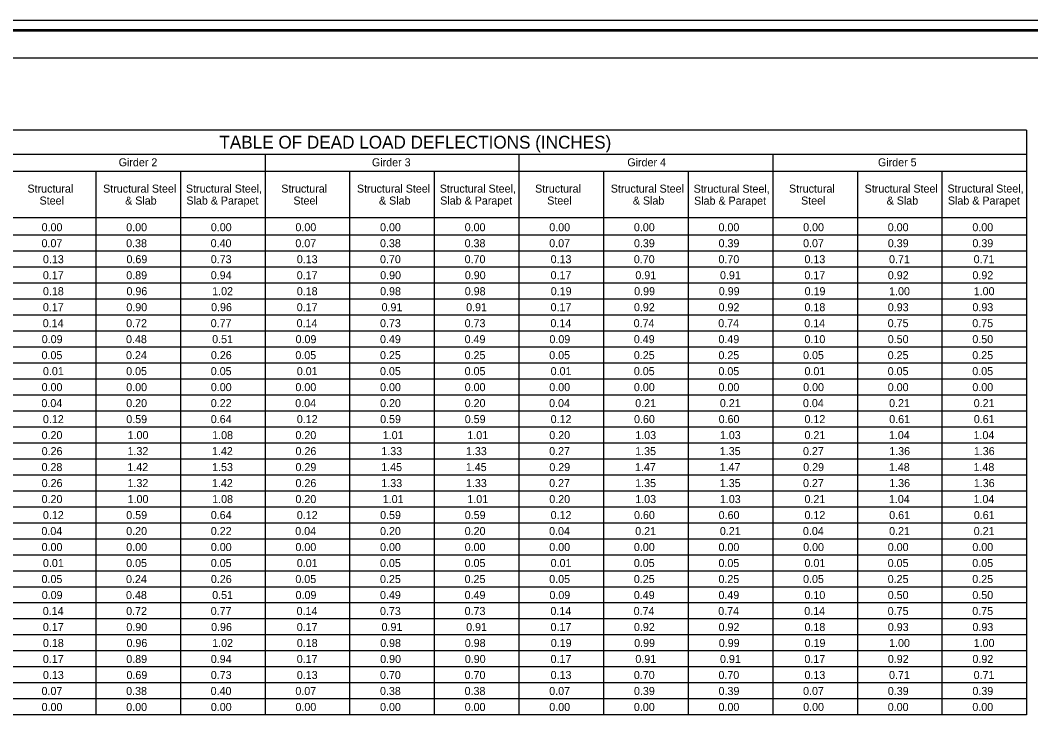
# Model space of a CAD drawing. Extents: x 208.5 to 250.5, y 328.7 to 350.7.
# Drawn here: x 216.62 to 232.41, y 339.65 to 350.71 of the extents above; entities that cross this region are included whole.
import ezdxf

# ---------------------------------------------------------------- set-up
doc = ezdxf.new("R2010")
doc.units = 0
for name, color, linetype in [('border', 7, 'Continuous'), ('Border 2660-Hwy18 - Level 62', 7, 'Continuous'), ('Border 2660-Hwy18 - Level 63', 7, 'Continuous'), ('Level 62 PDF', 7, 'Continuous'), ('Steel', 7, 'Continuous'), ('Text', 7, 'Continuous'), ('Title Text', 7, 'Continuous')]:
    doc.layers.add(name, color=color, linetype=linetype)

msp = doc.modelspace()

# ---------------------------------------------------------------- linework, layer by layer
at = {"layer": 'border'}
msp.add_line((210.28, 350.129), (242.291, 350.129), dxfattribs=at)
at = {"layer": 'Border 2660-Hwy18 - Level 62'}
msp.add_lwpolyline([(208.659, 350.715), (242.778, 350.715), (242.778, 328.905), (208.659, 328.905)], close=True, dxfattribs=at)
at = {"layer": 'Border 2660-Hwy18 - Level 63'}
msp.add_lwpolyline([(208.548, 350.572), (242.548, 350.572), (242.548, 329.202), (208.548, 329.202)], close=True, dxfattribs=at)
at = {"layer": 'Level 62 PDF'}
msp.add_lwpolyline([(208.909, 350.548), (243.028, 350.548), (243.028, 328.739), (208.909, 328.739)], close=True, dxfattribs=at)
at = {"layer": 'Steel'}
for p, q in [((232.347, 348.995), (210.932, 348.995)), ((232.347, 348.995), (232.347, 339.854)), ((232.347, 348.618), (210.932, 348.618)), ((220.449, 348.618), (220.449, 339.854)), ((224.415, 348.618), (224.415, 339.854)), ((228.381, 348.618), (228.381, 339.854)), ((232.347, 348.349), (212.517, 348.349)), ((217.805, 348.349), (217.805, 339.854)), ((219.127, 348.349), (219.127, 339.854)), ((221.771, 348.349), (221.771, 339.854)), ((223.093, 348.349), (223.093, 339.854)), ((225.737, 348.349), (225.737, 339.854)), ((227.059, 348.349), (227.059, 339.854)), ((229.703, 348.349), (229.703, 339.854)), ((231.025, 348.349), (231.025, 339.854)), ((232.347, 347.623), (210.932, 347.623)), ((232.347, 347.354), (211.725, 347.354)), ((232.347, 347.104), (211.725, 347.104)), ((232.347, 346.854), (211.725, 346.854)), ((232.347, 346.604), (211.725, 346.604)), ((232.347, 346.354), (211.725, 346.354)), ((232.347, 346.104), (211.725, 346.104)), ((232.347, 345.854), (211.725, 345.854)), ((232.347, 345.604), (211.725, 345.604)), ((232.347, 345.354), (211.725, 345.354)), ((232.347, 345.104), (211.725, 345.104)), ((232.347, 344.854), (211.725, 344.854)), ((232.347, 344.604), (211.725, 344.604)), ((232.347, 344.354), (211.725, 344.354)), ((232.347, 344.104), (211.725, 344.104)), ((232.347, 343.854), (211.725, 343.854)), ((232.347, 343.604), (211.725, 343.604)), ((232.347, 343.354), (211.725, 343.354)), ((232.347, 343.104), (211.725, 343.104)), ((232.347, 342.854), (211.725, 342.854)), ((232.347, 342.604), (211.725, 342.604)), ((232.347, 342.354), (211.725, 342.354)), ((232.347, 342.104), (211.725, 342.104)), ((232.347, 341.854), (211.725, 341.854)), ((232.347, 341.604), (211.725, 341.604)), ((232.347, 341.354), (211.725, 341.354)), ((232.347, 341.104), (211.725, 341.104)), ((232.347, 340.854), (211.725, 340.854)), ((232.347, 340.604), (211.725, 340.604)), ((232.347, 340.354), (211.725, 340.354)), ((232.347, 340.104), (211.725, 340.104)), ((232.347, 339.854), (210.932, 339.854))]:
    msp.add_line(p, q, dxfattribs=at)

# ---------------------------------------------------------------- texts
at = {"layer": 'Text'}
for s, p in [('Girder 2', (218.162, 348.431)), ('Girder 3', (222.119, 348.431)), ('Girder 4', (226.109, 348.431)), ('Girder 5', (230.025, 348.431)), ('Structural', (216.737, 348.02)), ('Structural Steel', (217.919, 348.02)), ('Structural Steel,', (219.213, 348.02)), ('Structural', (220.703, 348.02)), ('Structural Steel', (221.885, 348.02)), ('Structural Steel,', (223.179, 348.02)), ('Structural', (224.669, 348.02)), ('Structural Steel', (225.851, 348.02)), ('Structural Steel,', (227.145, 348.018)), ('Structural', (228.635, 348.02)), ('Structural Steel', (229.817, 348.02)), ('Structural Steel,', (231.111, 348.021)), ('Steel', (216.926, 347.833)), ('& Slab', (218.263, 347.833)), ('Slab & Parapet', (219.22, 347.833)), ('Steel', (220.892, 347.833)), ('& Slab', (222.229, 347.833)), ('Slab & Parapet', (223.186, 347.833)), ('Steel', (224.858, 347.833)), ('& Slab', (226.195, 347.833)), ('Slab & Parapet', (227.152, 347.831)), ('Steel', (228.824, 347.833)), ('& Slab', (230.161, 347.833)), ('Slab & Parapet', (231.118, 347.833)), ('0.00', (216.958, 347.416)), ('0.00', (218.28, 347.416)), ('0.00', (219.602, 347.416)), ('0.00', (220.924, 347.416)), ('0.00', (222.246, 347.416)), ('0.00', (223.568, 347.416)), ('0.00', (224.89, 347.416)), ('0.00', (226.212, 347.416)), ('0.00', (227.534, 347.416)), ('0.00', (228.856, 347.416)), ('0.00', (230.178, 347.416)), ('0.00', (231.5, 347.416)), ('0.07', (216.957, 347.166)), ('0.38', (218.279, 347.166)), ('0.40', (219.599, 347.166)), ('0.07', (220.923, 347.166)), ('0.38', (222.245, 347.166)), ('0.38', (223.567, 347.166)), ('0.07', (224.889, 347.166)), ('0.39', (226.213, 347.166)), ('0.39', (227.535, 347.166)), ('0.07', (228.855, 347.166)), ('0.39', (230.179, 347.166)), ('0.39', (231.501, 347.166)), ('0.13', (216.979, 346.916)), ('0.69', (218.284, 346.916)), ('0.73', (219.601, 346.916)), ('0.13', (220.945, 346.916)), ('0.70', (222.245, 346.916)), ('0.70', (223.567, 346.916)), ('0.13', (224.911, 346.916)), ('0.70', (226.211, 346.916)), ('0.70', (227.533, 346.916)), ('0.13', (228.877, 346.916)), ('0.71', (230.198, 346.916)), ('0.71', (231.52, 346.916)), ('0.17', (216.978, 346.666)), ('0.89', (218.281, 346.666)), ('0.94', (219.601, 346.666)), ('0.17', (220.944, 346.666)), ('0.90', (222.248, 346.666)), ('0.90', (223.57, 346.666)), ('0.17', (224.91, 346.666)), ('0.91', (226.235, 346.666)), ('0.91', (227.557, 346.666)), ('0.17', (228.876, 346.666)), ('0.92', (230.179, 346.666)), ('0.92', (231.501, 346.666)), ('0.18', (216.979, 346.416)), ('0.96', (218.284, 346.416)), ('1.02', (219.623, 346.416)), ('0.18', (220.945, 346.416)), ('0.98', (222.247, 346.416)), ('0.98', (223.569, 346.416)), ('0.19', (224.913, 346.416)), ('0.99', (226.216, 346.416)), ('0.99', (227.538, 346.416)), ('0.19', (228.879, 346.416)), ('1.00', (230.199, 346.416)), ('1.00', (231.521, 346.416)), ('0.17', (216.978, 346.166)), ('0.90', (218.282, 346.166)), ('0.96', (219.606, 346.166)), ('0.17', (220.944, 346.166)), ('0.91', (222.269, 346.166)), ('0.91', (223.591, 346.166)), ('0.17', (224.91, 346.166)), ('0.92', (226.213, 346.166)), ('0.92', (227.535, 346.166)), ('0.18', (228.877, 346.166)), ('0.93', (230.179, 346.166)), ('0.93', (231.501, 346.166)), ('0.14', (216.976, 345.916)), ('0.72', (218.279, 345.916)), ('0.77', (219.6, 345.916)), ('0.14', (220.942, 345.916)), ('0.73', (222.245, 345.916)), ('0.73', (223.567, 345.916)), ('0.14', (224.908, 345.916)), ('0.74', (226.208, 345.916)), ('0.74', (227.53, 345.916)), ('0.14', (228.874, 345.916)), ('0.75', (230.177, 345.916)), ('0.75', (231.499, 345.916)), ('0.09', (216.96, 345.666)), ('0.48', (218.277, 345.666)), ('0.51', (219.623, 345.666)), ('0.09', (220.926, 345.666)), ('0.49', (222.245, 345.666)), ('0.49', (223.567, 345.666)), ('0.09', (224.892, 345.666)), ('0.49', (226.211, 345.666)), ('0.49', (227.533, 345.666)), ('0.10', (228.877, 345.666)), ('0.50', (230.178, 345.666)), ('0.50', (231.5, 345.666)), ('0.05', (216.957, 345.416)), ('0.24', (218.277, 345.416)), ('0.26', (219.603, 345.416)), ('0.05', (220.923, 345.416)), ('0.25', (222.245, 345.416)), ('0.25', (223.567, 345.416)), ('0.05', (224.889, 345.416)), ('0.25', (226.211, 345.416)), ('0.25', (227.533, 345.416)), ('0.05', (228.855, 345.416)), ('0.25', (230.177, 345.416)), ('0.25', (231.499, 345.416)), ('0.01', (216.979, 345.166)), ('0.05', (218.279, 345.166)), ('0.05', (219.601, 345.166)), ('0.01', (220.945, 345.166)), ('0.05', (222.245, 345.166)), ('0.05', (223.567, 345.166)), ('0.01', (224.911, 345.166)), ('0.05', (226.211, 345.166)), ('0.05', (227.533, 345.166)), ('0.01', (228.877, 345.166)), ('0.05', (230.177, 345.166)), ('0.05', (231.499, 345.166)), ('0.00', (216.958, 344.916)), ('0.00', (218.28, 344.916)), ('0.00', (219.602, 344.916)), ('0.00', (220.924, 344.916)), ('0.00', (222.246, 344.916)), ('0.00', (223.568, 344.916)), ('0.00', (224.89, 344.916)), ('0.00', (226.212, 344.916)), ('0.00', (227.534, 344.916)), ('0.00', (228.856, 344.916)), ('0.00', (230.178, 344.916)), ('0.00', (231.5, 344.916)), ('0.04', (216.955, 344.666)), ('0.20', (218.28, 344.666)), ('0.22', (219.601, 344.666)), ('0.04', (220.921, 344.666)), ('0.20', (222.246, 344.666)), ('0.20', (223.568, 344.666)), ('0.04', (224.887, 344.666)), ('0.21', (226.233, 344.666)), ('0.21', (227.555, 344.666)), ('0.04', (228.853, 344.666)), ('0.21', (230.199, 344.666)), ('0.21', (231.521, 344.666)), ('0.12', (216.979, 344.416)), ('0.59', (218.281, 344.416)), ('0.64', (219.601, 344.416)), ('0.12', (220.945, 344.416)), ('0.59', (222.247, 344.416)), ('0.59', (223.569, 344.416)), ('0.12', (224.911, 344.416)), ('0.60', (226.214, 344.416)), ('0.60', (227.536, 344.416)), ('0.12', (228.877, 344.416)), ('0.61', (230.201, 344.416)), ('0.61', (231.523, 344.416)), ('0.20', (216.958, 344.166)), ('1.00', (218.302, 344.166)), ('1.08', (219.623, 344.166)), ('0.20', (220.924, 344.166)), ('1.01', (222.288, 344.166)), ('1.01', (223.61, 344.166)), ('0.20', (224.89, 344.166)), ('1.03', (226.233, 344.166)), ('1.03', (227.555, 344.166)), ('0.21', (228.877, 344.166)), ('1.04', (230.196, 344.166)), ('1.04', (231.518, 344.166)), ('0.26', (216.959, 343.916)), ('1.32', (218.3, 343.916)), ('1.42', (219.62, 343.916)), ('0.26', (220.925, 343.916)), ('1.33', (222.266, 343.916)), ('1.33', (223.588, 343.916)), ('0.27', (224.888, 343.916)), ('1.35', (226.232, 343.916)), ('1.35', (227.554, 343.916)), ('0.27', (228.854, 343.916)), ('1.36', (230.201, 343.916)), ('1.36', (231.523, 343.916)), ('0.28', (216.957, 343.666)), ('1.42', (218.298, 343.666)), ('1.53', (219.622, 343.666)), ('0.29', (220.925, 343.666)), ('1.45', (222.264, 343.666)), ('1.45', (223.586, 343.666)), ('0.29', (224.891, 343.666)), ('1.47', (226.229, 343.666)), ('1.47', (227.551, 343.666)), ('0.29', (228.857, 343.666)), ('1.48', (230.196, 343.666)), ('1.48', (231.518, 343.666)), ('0.26', (216.959, 343.416)), ('1.32', (218.3, 343.416)), ('1.42', (219.62, 343.416)), ('0.26', (220.925, 343.416)), ('1.33', (222.266, 343.416)), ('1.33', (223.588, 343.416)), ('0.27', (224.888, 343.416)), ('1.35', (226.232, 343.416)), ('1.35', (227.554, 343.416)), ('0.27', (228.854, 343.416)), ('1.36', (230.201, 343.416)), ('1.36', (231.523, 343.416)), ('0.20', (216.958, 343.166)), ('1.00', (218.302, 343.166)), ('1.08', (219.623, 343.166)), ('0.20', (220.924, 343.166)), ('1.01', (222.288, 343.166)), ('1.01', (223.61, 343.166)), ('0.20', (224.89, 343.166)), ('1.03', (226.233, 343.166)), ('1.03', (227.555, 343.166)), ('0.21', (228.877, 343.166)), ('1.04', (230.196, 343.166)), ('1.04', (231.518, 343.166)), ('0.12', (216.979, 342.916)), ('0.59', (218.281, 342.916)), ('0.64', (219.601, 342.916)), ('0.12', (220.945, 342.916)), ('0.59', (222.247, 342.916)), ('0.59', (223.569, 342.916)), ('0.12', (224.911, 342.916)), ('0.60', (226.214, 342.916)), ('0.60', (227.536, 342.916)), ('0.12', (228.877, 342.916)), ('0.61', (230.201, 342.916)), ('0.61', (231.523, 342.916)), ('0.04', (216.955, 342.666)), ('0.20', (218.28, 342.666)), ('0.22', (219.601, 342.666)), ('0.04', (220.921, 342.666)), ('0.20', (222.246, 342.666)), ('0.20', (223.568, 342.666)), ('0.04', (224.887, 342.666)), ('0.21', (226.233, 342.666)), ('0.21', (227.555, 342.666)), ('0.04', (228.853, 342.666)), ('0.21', (230.199, 342.666)), ('0.21', (231.521, 342.666)), ('0.00', (216.958, 342.416)), ('0.00', (218.28, 342.416)), ('0.00', (219.602, 342.416)), ('0.00', (220.924, 342.416)), ('0.00', (222.246, 342.416)), ('0.00', (223.568, 342.416)), ('0.00', (224.89, 342.416)), ('0.00', (226.212, 342.416)), ('0.00', (227.534, 342.416)), ('0.00', (228.856, 342.416)), ('0.00', (230.178, 342.416)), ('0.00', (231.5, 342.416)), ('0.01', (216.979, 342.166)), ('0.05', (218.279, 342.166)), ('0.05', (219.601, 342.166)), ('0.01', (220.945, 342.166)), ('0.05', (222.245, 342.166)), ('0.05', (223.567, 342.166)), ('0.01', (224.911, 342.166)), ('0.05', (226.211, 342.166)), ('0.05', (227.533, 342.166)), ('0.01', (228.877, 342.166)), ('0.05', (230.177, 342.166)), ('0.05', (231.499, 342.166)), ('0.05', (216.957, 341.916)), ('0.24', (218.277, 341.916)), ('0.26', (219.603, 341.916)), ('0.05', (220.923, 341.916)), ('0.25', (222.245, 341.916)), ('0.25', (223.567, 341.916)), ('0.05', (224.889, 341.916)), ('0.25', (226.211, 341.916)), ('0.25', (227.533, 341.916)), ('0.05', (228.855, 341.916)), ('0.25', (230.177, 341.916)), ('0.25', (231.499, 341.916)), ('0.09', (216.96, 341.666)), ('0.48', (218.277, 341.666)), ('0.51', (219.623, 341.666)), ('0.09', (220.926, 341.666)), ('0.49', (222.245, 341.666)), ('0.49', (223.567, 341.666)), ('0.09', (224.892, 341.666)), ('0.49', (226.211, 341.666)), ('0.49', (227.533, 341.666)), ('0.10', (228.877, 341.666)), ('0.50', (230.178, 341.666)), ('0.50', (231.5, 341.666)), ('0.14', (216.976, 341.416)), ('0.72', (218.279, 341.416)), ('0.77', (219.6, 341.416)), ('0.14', (220.942, 341.416)), ('0.73', (222.245, 341.416)), ('0.73', (223.567, 341.416)), ('0.14', (224.908, 341.416)), ('0.74', (226.208, 341.416)), ('0.74', (227.53, 341.416)), ('0.14', (228.874, 341.416)), ('0.75', (230.177, 341.416)), ('0.75', (231.499, 341.416)), ('0.17', (216.978, 341.166)), ('0.90', (218.282, 341.166)), ('0.96', (219.606, 341.166)), ('0.17', (220.944, 341.166)), ('0.91', (222.269, 341.166)), ('0.91', (223.591, 341.166)), ('0.17', (224.91, 341.166)), ('0.92', (226.213, 341.166)), ('0.92', (227.535, 341.166)), ('0.18', (228.877, 341.166)), ('0.93', (230.179, 341.166)), ('0.93', (231.501, 341.166)), ('0.18', (216.979, 340.916)), ('0.96', (218.284, 340.916)), ('1.02', (219.623, 340.916)), ('0.18', (220.945, 340.916)), ('0.98', (222.247, 340.916)), ('0.98', (223.569, 340.916)), ('0.19', (224.913, 340.916)), ('0.99', (226.216, 340.916)), ('0.99', (227.538, 340.916)), ('0.19', (228.879, 340.916)), ('1.00', (230.199, 340.916)), ('1.00', (231.521, 340.916)), ('0.17', (216.978, 340.666)), ('0.89', (218.281, 340.666)), ('0.94', (219.601, 340.666)), ('0.17', (220.944, 340.666)), ('0.90', (222.248, 340.666)), ('0.90', (223.57, 340.666)), ('0.17', (224.91, 340.666)), ('0.91', (226.235, 340.666)), ('0.91', (227.557, 340.666)), ('0.17', (228.876, 340.666)), ('0.92', (230.179, 340.666)), ('0.92', (231.501, 340.666)), ('0.13', (216.979, 340.416)), ('0.69', (218.284, 340.416)), ('0.73', (219.601, 340.416)), ('0.13', (220.945, 340.416)), ('0.70', (222.245, 340.416)), ('0.70', (223.567, 340.416)), ('0.13', (224.911, 340.416)), ('0.70', (226.211, 340.416)), ('0.70', (227.533, 340.416)), ('0.13', (228.877, 340.416)), ('0.71', (230.198, 340.416)), ('0.71', (231.52, 340.416)), ('0.07', (216.957, 340.166)), ('0.38', (218.279, 340.166)), ('0.40', (219.599, 340.166)), ('0.07', (220.923, 340.166)), ('0.38', (222.245, 340.166)), ('0.38', (223.567, 340.166)), ('0.07', (224.889, 340.166)), ('0.39', (226.213, 340.166)), ('0.39', (227.535, 340.166)), ('0.07', (228.855, 340.166)), ('0.39', (230.179, 340.166)), ('0.39', (231.501, 340.166)), ('0.00', (216.958, 339.916)), ('0.00', (218.28, 339.916)), ('0.00', (219.602, 339.916)), ('0.00', (220.924, 339.916)), ('0.00', (222.246, 339.916)), ('0.00', (223.568, 339.916)), ('0.00', (224.89, 339.916)), ('0.00', (226.212, 339.916)), ('0.00', (227.534, 339.916)), ('0.00', (228.856, 339.916)), ('0.00', (230.178, 339.916)), ('0.00', (231.5, 339.916))]:
    msp.add_text(s, height=0.125, dxfattribs=at).set_placement(p)
at = {"layer": 'Title Text'}
msp.add_text('TABLE OF DEAD LOAD DEFLECTIONS (INCHES)', height=0.2, dxfattribs=at).set_placement((219.736, 348.708))

doc.saveas('drawing.dxf')
